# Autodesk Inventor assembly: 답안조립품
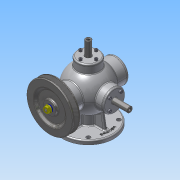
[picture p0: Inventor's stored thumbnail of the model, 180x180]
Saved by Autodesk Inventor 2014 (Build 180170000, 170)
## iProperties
Created: 2016-01
Part Number: 답안조립품
Document SubType Name: Assembly
Designer: Administrator
Author: Administrator
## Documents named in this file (17)
- C:\Users\Administrator\Desktop\360108V1017\답안조립품.iam
- C:\Users\Administrator\Desktop\360108V1017\본체.ipt
- C:\Users\Administrator\Desktop\360108V1017\V-벨트풀리.ipt
- C:\Users\Administrator\Desktop\360108V1017\너트-M8x1.ipt
- C:\Users\Administrator\Desktop\360108V1017\뒤커버.ipt
- C:\Users\Administrator\Desktop\360108V1017\베어링- 6202.ipt
- C:\Users\Administrator\Desktop\360108V1017\본체커버.ipt
- C:\Users\Administrator\Desktop\360108V1017\볼트 M4x0.7.ipt
- C:\Users\Administrator\Desktop\360108V1017\스프링1.ipt
- C:\Users\Administrator\Desktop\360108V1017\스프링2.ipt
- C:\Users\Administrator\Desktop\360108V1017\슬라이드 커버.ipt
- C:\Users\Administrator\Desktop\360108V1017\슬라이드.ipt
- C:\Users\Administrator\Desktop\360108V1017\앞커버.ipt
- C:\Users\Administrator\Desktop\360108V1017\오일실.ipt
- C:\Users\Administrator\Desktop\360108V1017\와셔 8x17.ipt
- C:\Users\Administrator\Desktop\360108V1017\축.ipt
- C:\Users\Administrator\Desktop\360108V1017\키-4x4.ipt
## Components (18 placed, 2 different names)
1. V-벨트풀리:1 — 플러쉬:18, 각도:2
2. M4x0.7x12:1
3. M4x0.7x12:2
4. M4x0.7x12:6
5. M4x0.7x12:7
6. M4x0.7x12:8
7. M4x0.7x12:3
8. M4x0.7x12:9
9. M4x0.7x12:10
10. M4x0.7x12:11
11. M4x0.7x12:4
12. M4x0.7x12:12
13. M4x0.7x12:13
14. M4x0.7x12:14
15. M4x0.7x12:5
16. M4x0.7x12:15
17. M4x0.7x12:16
18. M4x0.7x12:17
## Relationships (2: Flush 1, Angle 1)
- 플러쉬:18 [Flush]: V-벨트풀리:1
- 각도:2 [Angle]: V-벨트풀리:1
